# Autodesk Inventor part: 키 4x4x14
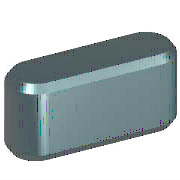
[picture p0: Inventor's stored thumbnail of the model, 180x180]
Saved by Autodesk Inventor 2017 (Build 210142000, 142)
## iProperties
IsCustomPart: 1
Created: 2012-02
Part Number: 키 4x4x14
Material: 강철, 연강
Description: 키 및 해당 키홈
Document SubType Name: Modeling
Standard: KS B 1311
Designer: mduedu
Standards Organization: KS
Language: ko-KR
Size Designation: 4 x 4 x 14
Categories: <MemberInstance><Categories><Category DisplayName="샤프트 부품" InternalName="7f7aeb1f-a693-4053-b835-cee3144e0d98" Mnemonic="SHFT"><Category DisplayName="키" Interna
Density: 1 g/cm^3
Appearance: 노란색
Author: mduedu
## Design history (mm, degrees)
workplane "Work Plane1"
workplane "Work Plane2"
sketch "스케치1"
  geometry: L1 (2, 2)-(12, 2); L2 (12, -2)-(2, -2); L3 (0, 9.4)-(0, -7.4) reference; L4 (-5, 0)-(30, 0) reference; L5 (14, 0)-(14, 7); A1 r 2 centre (2, 0) between (2, 2) and (2, -2); A2 r 2 centre (12, 0) between (12, -2) and (12, 2)
  constraints: 6 end point, 5 point on circle, 4 tangent, 3 point on line, 2 centre point, 1 horizontal, 1 parallel, 1 perpendicular
  dimensions: "d0" = 2 radius of A1 (= 0.5 x PB); "d13" = 2 radius of A2 (= 0.5 x PB); "d14" = 14 distance between parallel lines of L5 L3 (= NLG)
extrude "본체1" new body sketch "스케치1" taper "d3" = 0 deg; stored distance "d4" = 10
workplane "Work Plane3"
body "Solid1"
chamfer "모따기1" distance "d8" = 0.25 (= PHH); stored, may be unused: second distance "d9" = 0.25 (= PHH), angle "d15" = 45 deg
other parameters: "d1" = -2.5 (= -PNT), "d2" = 1.5 (= PH - PNT), "NLG" = 14 [user parameter; used in 3 equation terms], "PB" = 4 [user parameter; used in 2 equation terms], "PNT" = 2.5 [user parameter; used in 2 equation terms], "PH" = 4 [user parameter; used in 1 equation term], "PHH" = 0.25 [user parameter; used in 2 equation terms], "d10" = 0, "d16" = 0, "d17" = 0, "d18" = 0, "PLB2" = 14 (= NLG) [user parameter], "WDMAX" = 12 [user parameter], "PLB1" = 14 (= NLG) [user parameter], "RR" = 0.08 [user parameter], "PUEB" = 1.8 [user parameter]
